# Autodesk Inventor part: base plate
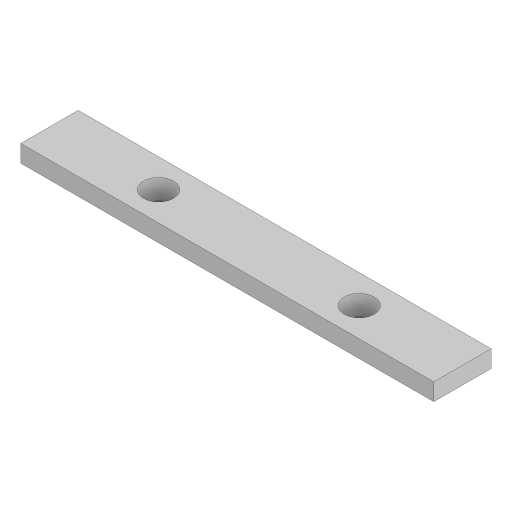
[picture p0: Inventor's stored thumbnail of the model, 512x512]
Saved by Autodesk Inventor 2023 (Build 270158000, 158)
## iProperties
Created: 2016-03
Part Number: base plate
Material: Generic
Document SubType Name: Modeling
Designer: Sandeep
Density: 1 g/cm^3
Appearance: Default
Mass: 16.6527 g
Surface Area: 78.2446 cm^2
Volume: 16.6527 cm^3
Author: Sandeep
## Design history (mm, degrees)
sketch "Sketch1"
  geometry: L1 (0, 0)-(144, 0); L2 (144, 0)-(144, 20); L3 (144, 20)-(0, 20); L4 (0, 20)-(0, 0)
  constraints: 8 end point, 2 parallel, 1 horizontal, 1 perpendicular
  dimensions: "d0" = 144 distance of L1.start L1.end; "d1" = 20 distance of L1.end L2.end
extrude "Extrusion1" new body sketch "Sketch1" distance "d2" = 6; taper "d3" = 0 deg
sketch "Sketch2"
  geometry: L1 (0, 20)-(0, 0) reference; L2 (0, 10)-(181.292, 10); 2 further points
  constraints: 2 end point, 2 point on line, 1 horizontal, 1 midpoint
  dimensions: "d4" = 70 distance of point (108, 10) point (38, 10); "d5" = 38 distance from line of L1 point (38, 10)
hole "Hole1" sketch "Sketch2" at (38, 10), (108, 10) diameter "d6" = 6; stored, may be unused: countersink angle "d10" = 45 deg, drill point angle "d12" = 118 deg; dims "d7" = 6, "d8" = 10.5, "d9" = 2, "d11" = 8
body "Solid1"
